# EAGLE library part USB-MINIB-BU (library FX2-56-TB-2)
USB-MiniB-Buchse Oberflächenmontage irregulär von unten in Leiterplatten-Ausschnitt
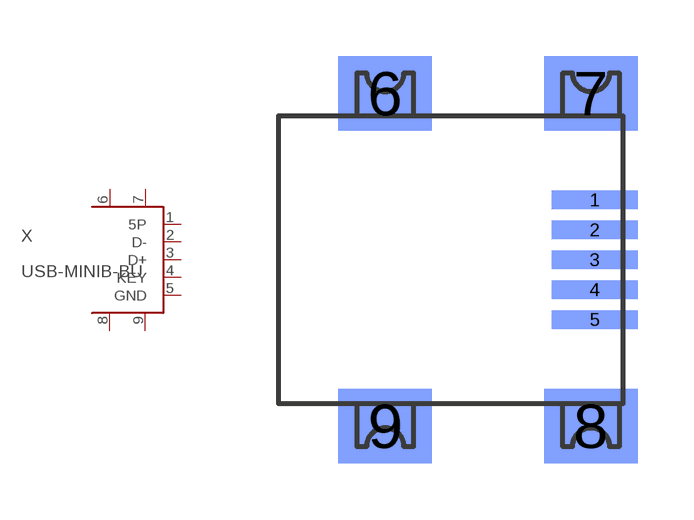
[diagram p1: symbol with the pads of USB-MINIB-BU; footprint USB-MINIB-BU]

Designator prefix X

## USB-MINIB-BU  [USB-MINIB-BU]
1  5P  sup
2  D-
3  D+
4  KEY
5  GND  pwr
6  GND  pwr
7  GND  pwr
8  GND  pwr
9  GND  pwr

## Footprint USB-MINIB-BU (pad centres in mm)
USB-MiniB-Buchse Oberflächenmontage irregulär von unten in Leiterplatten-Ausschnitt
smd 2.3 x 0.5 bottom: 1 7.85,1.6; 2 7.85,0.8; 3 7.85,0; 4 7.85,-0.8; 5 7.85,-1.6
smd 2.5 x 2 bottom: 6 2.25,4.45; 7 7.75,4.45; 8 7.75,-4.45; 9 2.25,-4.45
